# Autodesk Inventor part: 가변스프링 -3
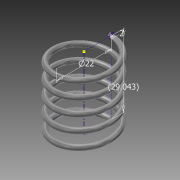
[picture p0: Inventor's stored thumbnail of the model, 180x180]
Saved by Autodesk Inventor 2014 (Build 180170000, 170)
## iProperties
Created: 2016-01
Part Number: 가변스프링 -3
Material: 스테인레스 스틸
Document SubType Name: Modeling
Designer: Administrator
Density: 8.08 g/cm^3
Appearance: 반연마
Mass: 8.62004 g
Surface Area: 21.6891 cm^2
Volume: 1.06684 cm^3
Author: Administrator
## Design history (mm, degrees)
sketch "스케치1"
  geometry: L1 (0, -29.043)-(11, -29.043); L2 (11, -29.043)-(11, 0); L3 (11, 0)-(0, 0); L4 (0, 0)-(0, -29.043); C1 r 1 at (11, 0); 1 further point
  constraints: 8 end point, 2 coincident, 2 parallel, 1 centre point, 1 horizontal, 1 perpendicular
  dimensions: "d0" = 2 diameter of C1; "d1" = 22 diameter of L2 L4; "d2" = 29.04259 distance of L1.end L2.end (derived)
feature "코일1" pitch "d3" = 10; turns "d5" = 5; dims "d4" = 29.04259 (= d2), "d6" = 0, angle "d7" = 90 deg, angle "d8" = 90 deg, "d9" = 0, "d10" = 0
sketch "스케치4"
  geometry: L1 (0, 10)-(0, 12) reference; 1 further point
  constraints: 1 vertical alignment
extrude "돌출3" cut sketch "스케치4" distance "d16" = 10; taper "d17" = 0 deg
node "작업 평면2"
sketch "스케치5"
  geometry: L1 (12, 0)-(10, 0) reference; 1 further point
  constraints: 1 horizontal alignment
extrude "돌출4" cut sketch "스케치5" distance "d19" = 10; taper "d20" = 0 deg
node "솔리드1"
node "절단 모서리 투영3"
node "절단 모서리 투영4"
other parameters: "d18" = 0
